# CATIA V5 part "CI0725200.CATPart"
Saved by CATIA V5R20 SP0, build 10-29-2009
Part number: CI0725200
Bounding box of the stored display mesh (mm): x -24 to 24, y -20.111 to 234.5, z -24.221 to 28.662
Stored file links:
  C:\Users\Raffaele\Desktop\3D X SITO CF\BOLEX\19-INCLINED ASSEMBLY REF_CI\CI0725200.CATPart
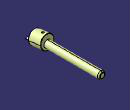
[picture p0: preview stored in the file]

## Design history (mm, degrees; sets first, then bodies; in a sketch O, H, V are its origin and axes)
Set1
  DatumSurface1 to DatumSurface16 "MANIFOLD_SOLID_BREP #393"
  DatumSurface17 to DatumSurface39 "MANIFOLD_SOLID_BREP #1138"
Body1 (main body)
